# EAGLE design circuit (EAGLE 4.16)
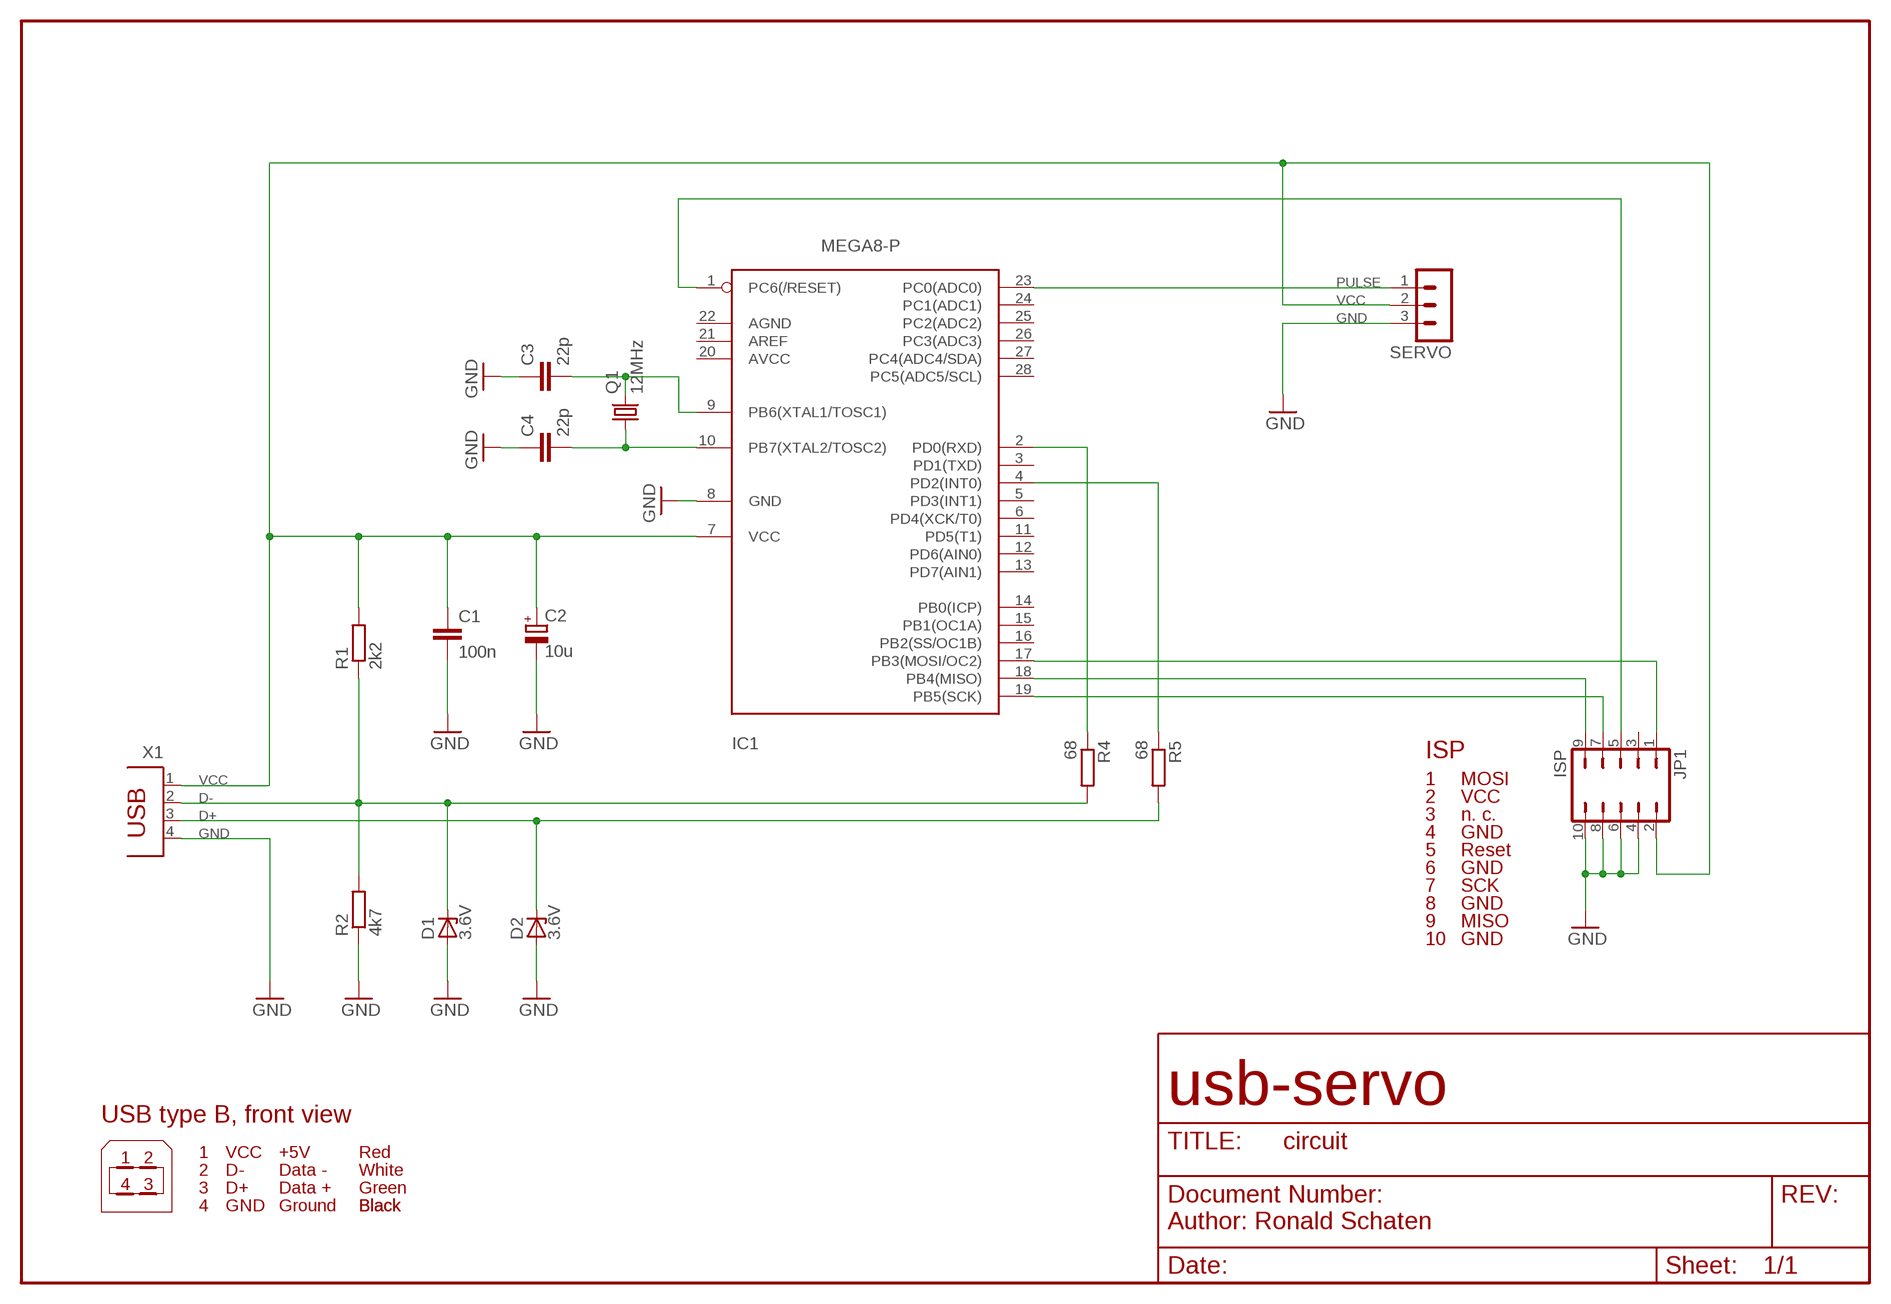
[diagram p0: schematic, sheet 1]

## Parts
C1  100n  C-EU025-024X044  [C025-024X044]
C2  10u  CPOL-EUE2.5-5  [E2,5-5]
C3  22p  C-EU025-024X044  [C025-024X044]
C4  22p  C-EU025-024X044  [C025-024X044]
D1  3.6V  ZENER-DIODEDO35Z10  [DO35Z10]
D2  3.6V  ZENER-DIODEDO35Z10  [DO35Z10]
IC1  MEGA8-P  [DIL28-3]
JP1  ISP  JP5Q  [JP5Q]
Q1  12MHz  CRYTALHC18U-V  [HC18U-V]
R1  2k2  R-EU_0207/10  [0207/10]
R2  4k7  R-EU_0207/10  [0207/10]
R4  68  R-EU_0207/10  [0207/10]
R5  68  R-EU_0207/10  [0207/10]
SERVO  MA03-1  [MA03-1]
X1  PN61729  [PN61729]

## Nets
D+: D2.C R5.2 X1.3
D-: D1.C R1.1 R2.2 R4.2 X1.2
GND: C1.2 C2.- C3.1 C4.1 D1.A D2.A IC1.8(GND) JP1.4 JP1.6 JP1.8 JP1.10 R2.1 SERVO.3 X1.4
N$1: IC1.2(PD0(RXD)) R4.1
N$2: C3.2 IC1.9(PB6(XTAL1/TOSC1)) Q1.2
N$7: C4.2 IC1.10(PB7(XTAL2/TOSC2)) Q1.1
N$9: IC1.4(PD2(INT0)) R5.1
N$11: IC1.17(PB3(MOSI/OC2)) JP1.1
N$12: IC1.1(PC6(/RESET)) JP1.5
N$18: IC1.19(PB5(SCK)) JP1.7
N$22: IC1.18(PB4(MISO)) JP1.9
PULSE: IC1.23(PC0(ADC0)) SERVO.1
VCC: C1.1 C2.+ IC1.7(VCC) JP1.2 R1.2 SERVO.2 X1.1
Unconnected: IC1.3(PD1(TXD)) IC1.5(PD3(INT1)) IC1.6(PD4(XCK/T0)) IC1.11(PD5(T1)) IC1.12(PD6(AIN0)) IC1.13(PD7(AIN1)) IC1.14(PB0(ICP)) IC1.15(PB1(OC1A)) IC1.16(PB2(SS/OC1B)) IC1.20(AVCC) IC1.21(AREF) IC1.22(AGND) IC1.24(PC1(ADC1)) IC1.25(PC2(ADC2)) IC1.26(PC3(ADC3)) IC1.27(PC4(ADC4/SDA)) IC1.28(PC5(ADC5/SCL)) JP1.3

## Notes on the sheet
- ISP
- 1 | MOSI
- 2 | VCC
- 3 | n. c.
- 4 | GND
- 5 | Reset
- 6 | GND
- 7 | SCK
- 8 | GND
- 9 | MISO
- 10 | GND
- usb-servo
- USB type B, front view
- 1 | VCC | +5V | Red
- 1 | 2
- 2 | D- | Data - | White
- 4 | 3 | 3 | D+ | Data + | Green
- 4 | GND | Ground | Black | Black
- Author: Ronald Schaten

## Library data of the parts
C1 C3 C4 = rcl:C-EU: CAPACITOR, European symbol
C2 = rcl:CPOL-EU: POLARIZED CAPACITOR, European symbol
D1 D2 = diode:ZENER-DIODE: Z-Diode
IC1 = avr:MEGA8-P: MICROCONTROLLER 8 Kbytes FLASH 1 kbytes SRAM 512 bytes EEPROM USART 4-channel 10 bit ADC 2-channel 8 bit ADC
JP1 = jumper:JP5Q: JUMPER
Q1 = crystal:CRYTAL: CRYSTAL
R1 R2 R4 R5 = rcl:R-EU_: RESISTOR, European symbol
SERVO = con-lstb:MA03-1: PIN HEADER
X1 = con-berg:PN61729: BERG USB connector

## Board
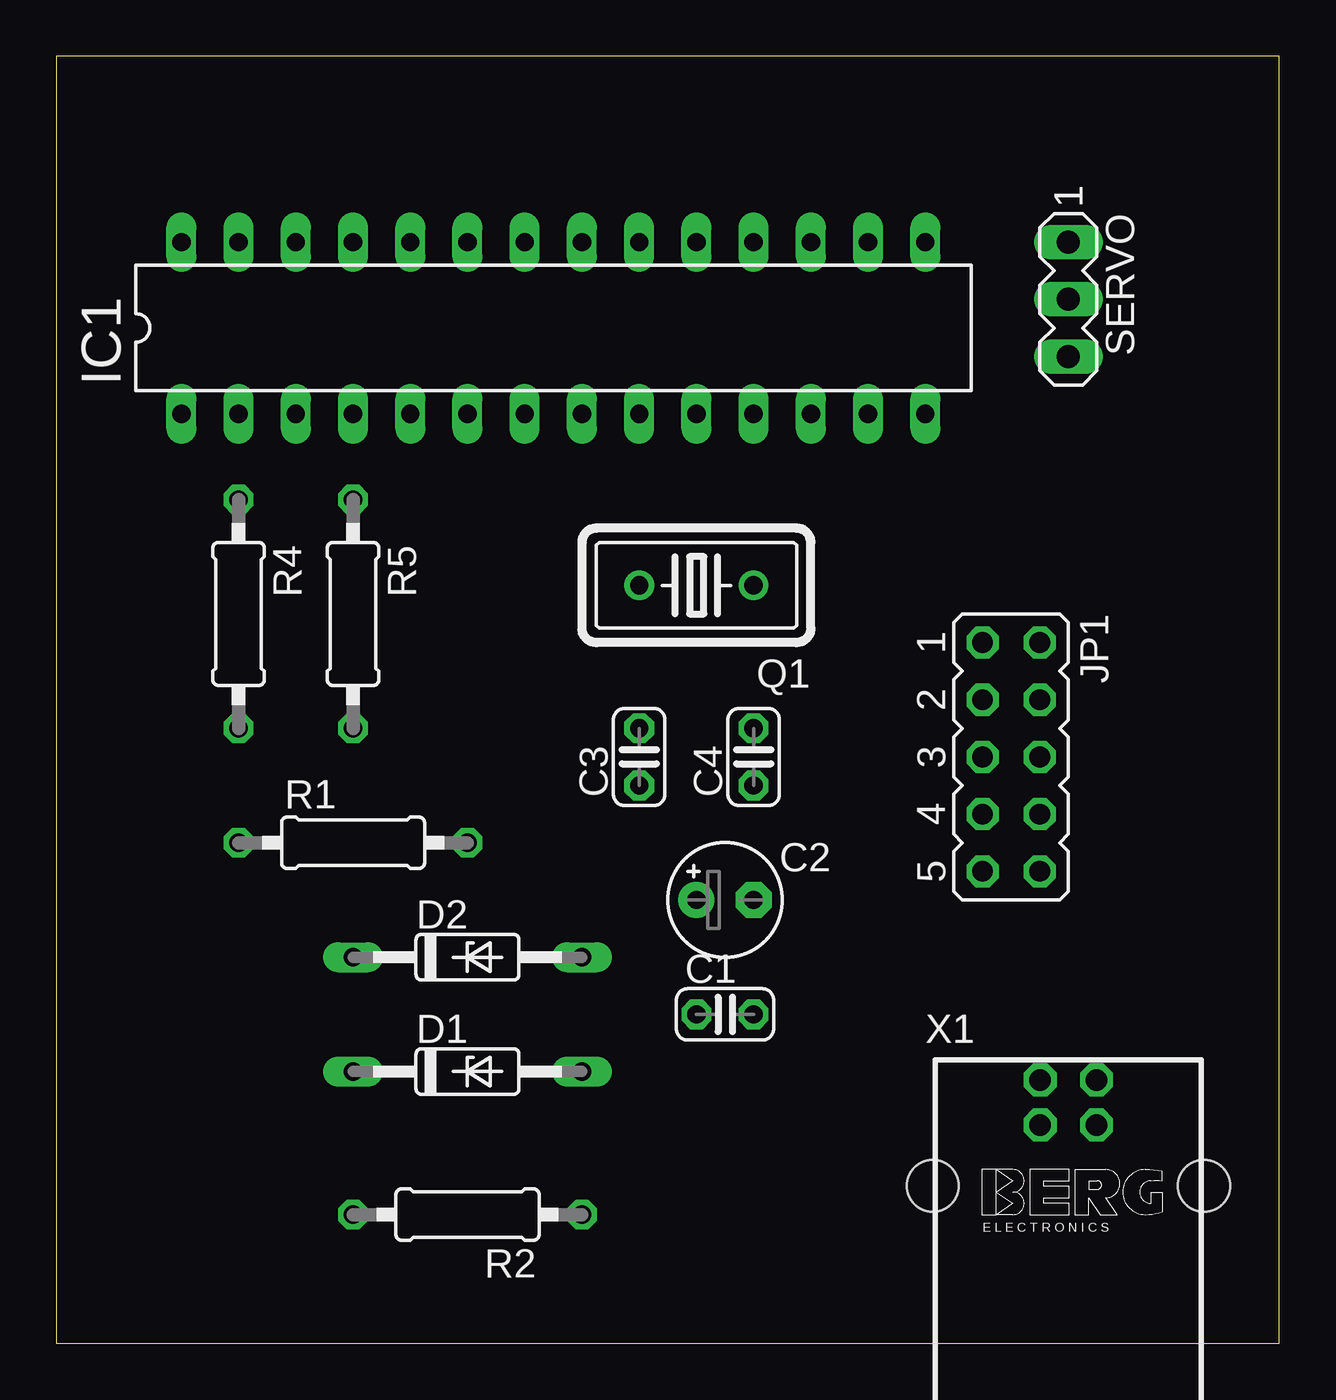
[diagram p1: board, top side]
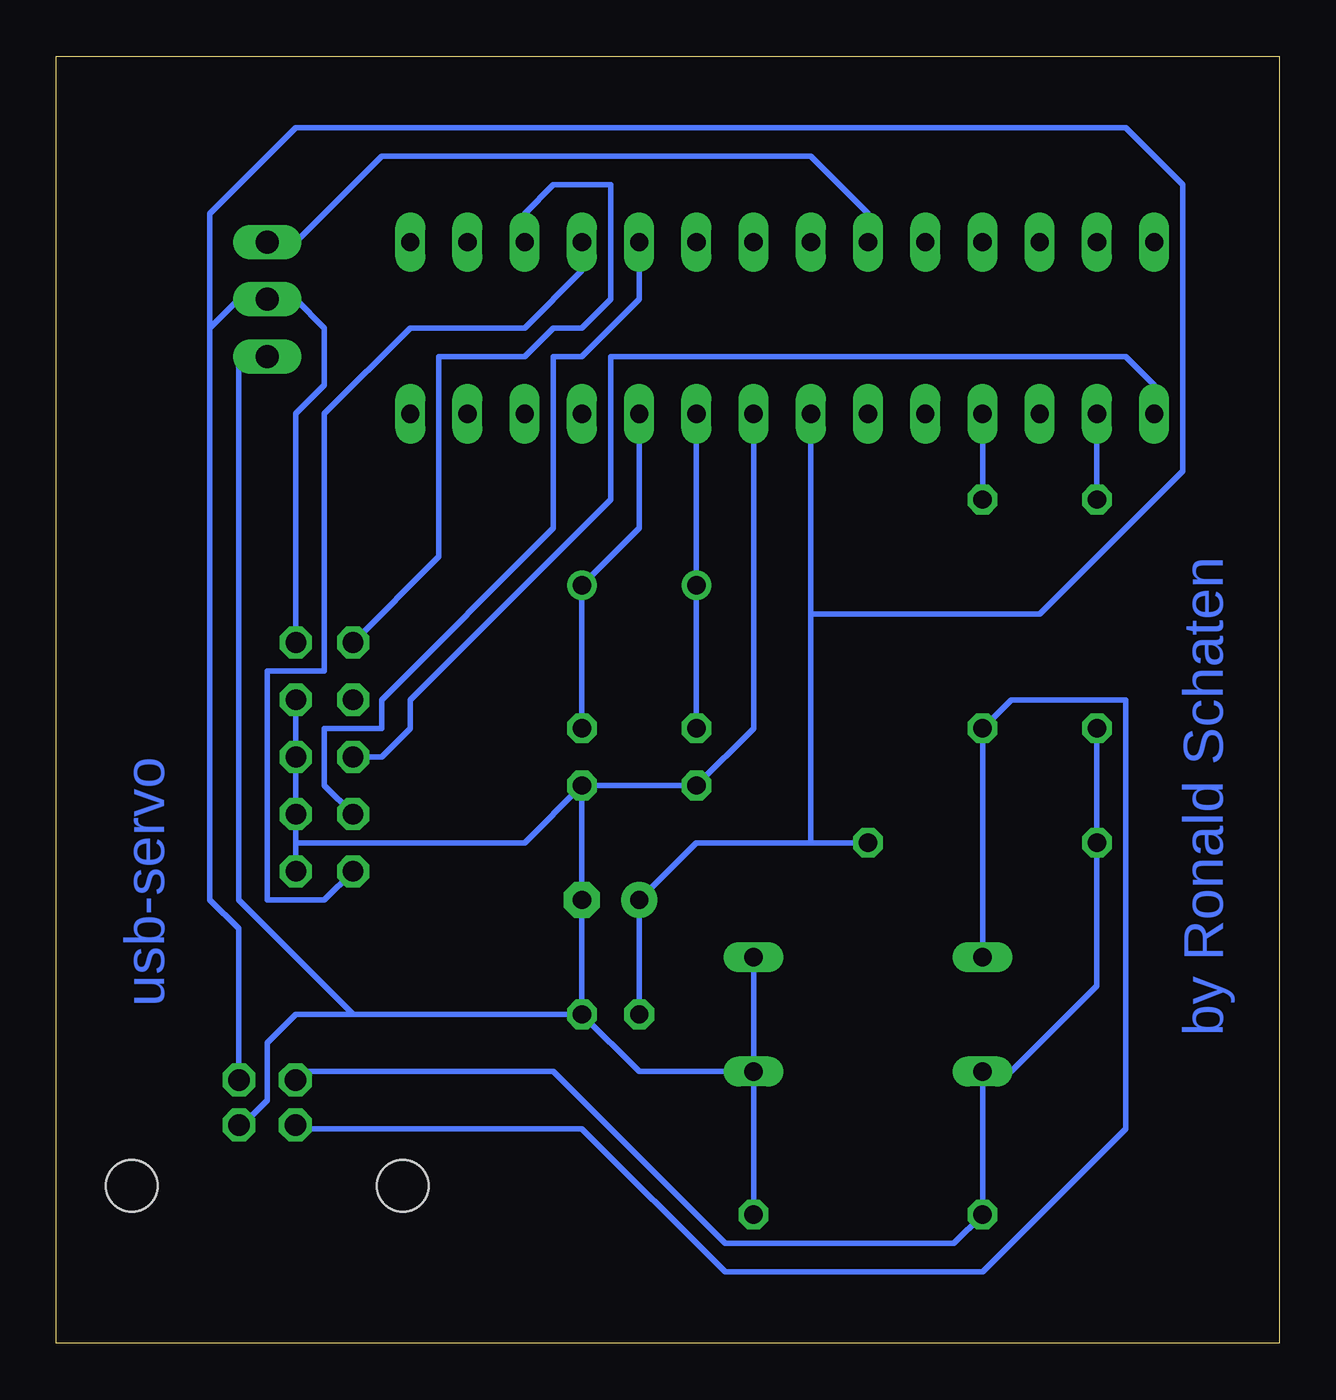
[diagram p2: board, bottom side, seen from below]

Size 54.28 x 57.14 mm. Coordinates in mm from the lower left corner, seen from the top.
Outline: 0,0 54.28,0 54.28,57.14 0,57.14 0,0
Copper layers (1*16): Top 0.035mm / dielectric 1.5mm / Bottom 0.035mm
Design rules "default": minimum track width 10mil, minimum drill 24mil, track to track 8mil, track to pad 8mil, pad to pad 8mil, via to via 8mil, smd to smd 8mil, copper to edge 40mil, drill to drill 8mil, minimum pad ring 10mil, minimum via ring 8mil, stop-mask expansion 4mil, vias tented up to drill 0mil, thermal gap 10mil

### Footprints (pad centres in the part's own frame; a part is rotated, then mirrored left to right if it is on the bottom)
C025-024X044 = drill 0.813 octagon: 1 -1.27,0; 2 1.27,0
E2,5-5 = drill 0.813 pad 1.6 round: + -1.27,0 | drill 0.813 pad 1.6 octagon: - 1.27,0
DO35Z10 = drill 0.813 long: A 5.08,0; C -5.08,0
DIL28-3 = drill 0.813 long: 1 -16.51,-3.81; 2 -13.97,-3.81; 3 -11.43,-3.81; 4 -8.89,-3.81; 5 -6.35,-3.81; 6 -3.81,-3.81; 7 -1.27,-3.81; 8 1.27,-3.81; 9 3.81,-3.81; 10 6.35,-3.81; 11 8.89,-3.81; 12 11.43,-3.81; 13 13.97,-3.81; 14 16.51,-3.81; 15 16.51,3.81; 16 13.97,3.81; 17 11.43,3.81; 18 8.89,3.81; 19 6.35,3.81; 20 3.81,3.81; 21 1.27,3.81; 22 -1.27,3.81; 23 -3.81,3.81; 24 -6.35,3.81; 25 -8.89,3.81; 26 -11.43,3.81; 27 -13.97,3.81; 28 -16.51,3.81
JP5Q = drill 0.914 octagon: 1 -5.08,-1.27; 2 -5.08,1.27; 3 -2.54,-1.27; 4 -2.54,1.27; 5 0,-1.27; 6 0,1.27; 7 2.54,-1.27; 8 2.54,1.27; 9 5.08,-1.27; 10 5.08,1.27
HC18U-V = drill 0.813 round: 1 -2.54,0; 2 2.54,0
0207/10 = drill 0.813 octagon: 1 -5.08,0; 2 5.08,0
MA03-1 = drill 1.016 long: 1 -2.54,0; 2 0,0; 3 2.54,0
PN61729 = drill 0.95 octagon: 1 1.25,4.71; 2 -1.25,4.71; 3 -1.25,2.71; 4 1.25,2.71 | hole 2.3: -6.02,0; 6.02,0

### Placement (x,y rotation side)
C1  29.68,14.6 0 top
C2  29.68,19.68 0 top
C3  25.87,26.03 90 top
C4  30.95,26.03 90 top
D1  18.25,12.06 0 top
D2  18.25,17.14 0 top
IC1  22.06,45.08 0 top
JP1  42.38,26.03 270 top
Q1  28.41,33.65 180 top
R1  13.17,22.22 0 top
R2  18.25,5.71 180 top
R4  8.09,32.38 270 top
R5  13.17,32.38 270 top
SERVO  44.92,46.35 270 top
X1  44.92,6.98 0 top

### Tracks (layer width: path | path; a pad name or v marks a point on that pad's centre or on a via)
D+
  Bottom 0.254: D2.C R5.2 11.9,28.57 6.82,28.57 6.82,9.52 13.17,3.17 24.6,3.17 30.95,9.52 43.65,9.52 X1.3
D-
  Bottom 0.254: R4.2 R1.1 8.09,15.87 11.9,12.06 D1.C R2.2 14.44,4.44 24.6,4.44 32.22,12.06 43.65,12.06 X1.2
GND
  Bottom 0.254: 43.65,22.22 JP1.8 JP1.6 JP1.4 | 43.65,22.22 JP1.10 | C4.1 C3.1 23.33,27.3 IC1.8 | 43.65,22.22 33.49,22.22 C4.1 | R2.1 D1.A | D1.A D2.A | C1.2 C2.- C4.1 | C1.2 41.11,14.6 | 41.11,14.6 43.65,14.6 44.92,13.33 44.92,10.79 46.19,9.52 X1.4 | 41.11,14.6 46.19,19.68 46.19,43.81 SERVO.3 | C1.2 28.41,12.06 D1.A
N$1
  Bottom 0.254: R4.1 IC1.2
N$2
  Bottom 0.254: C3.2 Q1.2 IC1.9
N$7
  Bottom 0.254: C4.2 Q1.1 28.41,36.19 IC1.10
N$9
  Bottom 0.254: R5.1 IC1.4
N$11
  Bottom 0.254: JP1.1 37.3,34.92 37.3,43.81 33.49,43.81 32.22,45.08 30.95,45.08 29.68,46.35 29.68,51.43 32.22,51.43 33.49,50.16 IC1.17
N$12
  Bottom 0.254: JP1.5 39.84,26.03 38.57,27.3 38.57,28.57 29.68,37.46 29.68,43.81 6.82,43.81 5.55,42.54 IC1.1
N$18
  Bottom 0.254: JP1.7 42.38,24.76 42.38,27.3 39.84,27.3 39.84,28.57 32.22,36.19 32.22,43.81 30.95,43.81 28.41,46.35 IC1.19
N$22
  Bottom 0.254: JP1.9 42.38,19.68 44.92,19.68 44.92,29.84 42.38,29.84 42.38,41.27 38.57,45.08 33.49,45.08 30.95,47.62 IC1.18
PULSE
  Bottom 0.254: IC1.23 18.25,50.16 20.79,52.7 39.84,52.7 43.65,48.89 SERVO.1
VCC
  Bottom 0.254: 20.79,22.22 25.87,22.22 C2.+ C1.1 | R1.2 20.79,22.22 | 20.79,22.22 20.79,32.38 | 20.79,32.38 IC1.7 | JP1.2 43.65,41.27 42.38,42.54 42.38,45.08 43.65,46.35 SERVO.2 46.19,46.35 47.46,45.08 | 47.46,45.08 47.46,19.68 46.19,18.41 46.19,12.06 X1.1 | 20.79,32.38 10.63,32.38 4.28,38.73 4.28,51.43 6.82,53.97 43.65,53.97 47.46,50.16 47.46,45.08

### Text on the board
Bottom: by Ronald Schaten | usb-servo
